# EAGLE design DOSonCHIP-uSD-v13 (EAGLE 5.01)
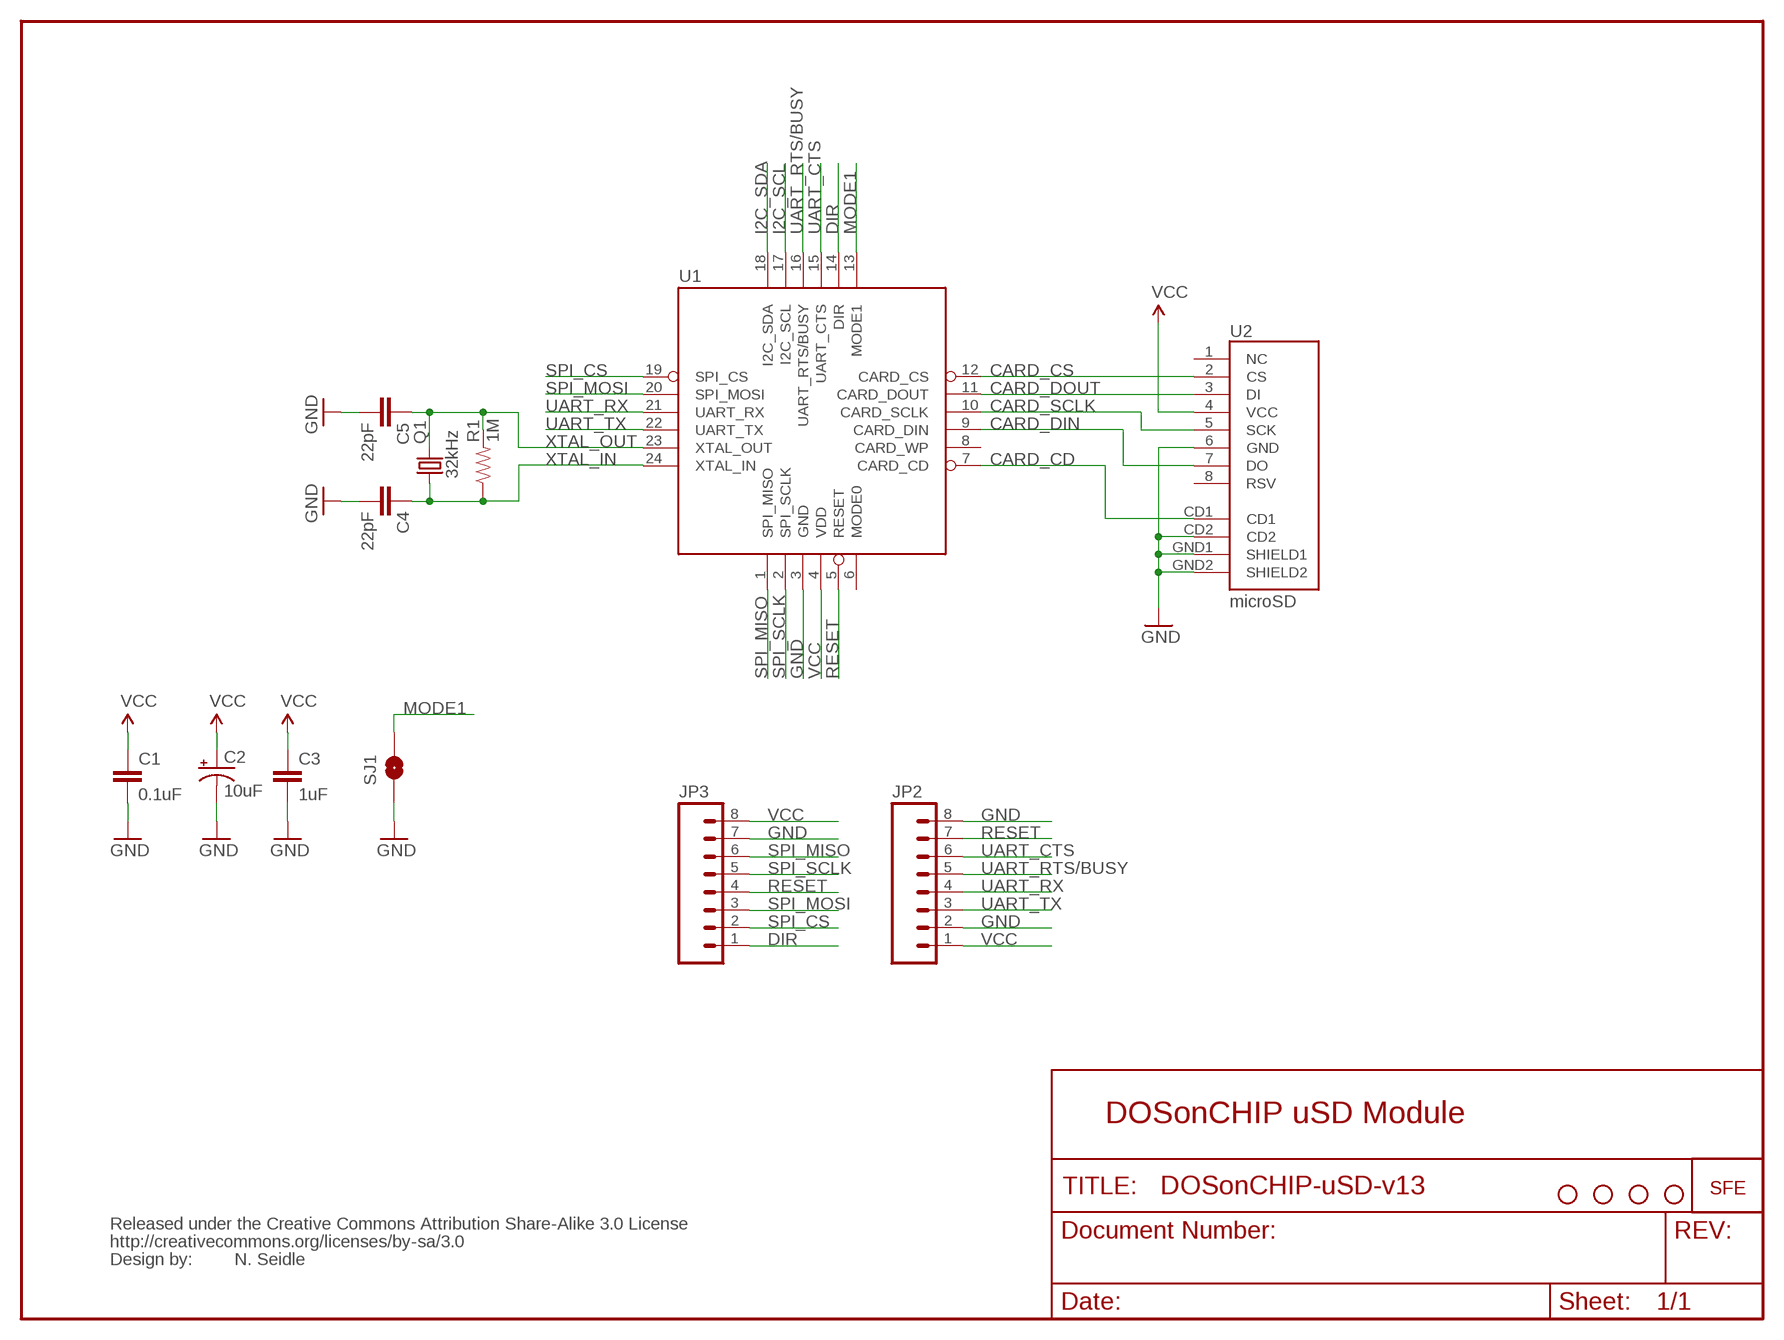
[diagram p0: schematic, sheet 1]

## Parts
C1  0.1uF  CAP0402  [C0402]
C2  10uF  CAP_POL1206  [EIA3216]
C3  1uF  CAP0402  [C0402]
C4  22pF  CAP0402  [C0402]
C5  22pF  CAP0402  [C0402]
JP2  M08  [1X08]
JP3  M08  [1X08]
Q1  32kHz  CRYSTAL32-SMD  [CRYSTAL-32KHZ-SMD]
R1  1M  RESISTOR0402  [C0402]
SJ1  SOLDERJUMPERNO2  [SJ_2S-NO]
U1  DOSONCHIP  DOSONCHIP-ICQFN  [QFN-24]
U2  microSD  USD-SOCKETUSD  [USD-SOCKET-PP]
U$1  LOGO-SFENEW  [SFE-NEW-WEBLOGO]
U$2  STAND-OFF  [STAND-OFF]
U$3  STAND-OFF  [STAND-OFF]
U$4  STAND-OFF  [STAND-OFF]
U$5  STAND-OFF  [STAND-OFF]
U$6  CREATIVE_COMMONS  [CREATIVE_COMMONS]

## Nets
CARD_CD: U1.7(CARD_CD) U2.CD1
CARD_CS: U1.12(CARD_CS) U2.2(CS)
CARD_DIN: U1.9(CARD_DIN) U2.7(DO)
CARD_DOUT: U1.11(CARD_DOUT) U2.3(DI)
CARD_SCLK: U1.10(CARD_SCLK) U2.5(SCK)
DIR: JP3.1 U1.14(DIR)
GND [power]: C1.2 C2.C(-) C3.2 C4.2 C5.2 JP2.2 JP2.8 JP3.7 SJ1.1 U1.3(GND) U2.6(GND) U2.CD2 U2.GND1(SHIELD1) U2.GND2(SHIELD2)
I2C_SCL: U1.17(I2C_SCL)
I2C_SDA: U1.18(I2C_SDA)
MODE1: SJ1.2 U1.13(MODE1)
RESET: JP2.7 JP3.4 U1.5(RESET)
SPI_CS: JP3.2 U1.19(SPI_CS)
SPI_MISO: JP3.6 U1.1(SPI_MISO)
SPI_MOSI: JP3.3 U1.20(SPI_MOSI)
SPI_SCLK: JP3.5 U1.2(SPI_SCLK)
UART_CTS: JP2.6 U1.15(UART_CTS)
UART_RTS/BUSY: JP2.5 U1.16(UART_RTS/BUSY)
UART_RX: JP2.4 U1.21(UART_RX)
UART_TX: JP2.3 U1.22(UART_TX)
VCC [power]: C1.1 C2.A(+) C3.1 JP2.1 JP3.8 U1.4(VDD) U2.4(VCC)
XTAL_IN: C4.1 Q1.X1 R1.1 U1.24(XTAL_IN)
XTAL_OUT: C5.1 Q1.X2 R1.2 U1.23(XTAL_OUT)
Unconnected: U1.6(MODE0) U1.8(CARD_WP) U2.1(NC) U2.8(RSV)

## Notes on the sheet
- DOSonCHIP uSD Module
- N. Seidle

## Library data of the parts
C1 C3-C5 = SparkFun:CAP: Capacitor
C2 = SparkFun:CAP_POL: Capacitor Polarized
JP2 JP3 = SparkFun:M08: Header 8 Standard 8-pin 0.1" header. Use with straight break away headers (SKU : PRT-00116), right angle break away headers (PRT-00553), swiss pins (PRT-00743), machine pins (PRT-00117), and female headers (PRT-00115).
Q1 = SparkFun:CRYSTAL: Crystals
R1 = SparkFun:RESISTOR: Resistor
SJ1 = SparkFun:SOLDERJUMPER: Solder Jumper
U1 = SparkFun:DOSONCHIP-IC: DOSonCHIP IC This is the tested schematic and footprint for the DOSonCHIP FAT16 FAT32 IC. Spark Fun Electronics SKU : COM-07956. QFN package also tested/proven.
U2 = SparkFun:USD-SOCKET: microSD Socket Push-push type uSD socket. Schematic element and footprint production proven. Spark Fun Electronics SKU : PRT-00127. tDoc lines correctly indicate media card edge positions when inserting (unlocked, locked, depressed).
U$1 = SparkFun:LOGO-SFE: Spark Fun Electronics PCB Logo
U$2-U$5 = SparkFun:STAND-OFF: Stand Off
U$6 = SparkFun:CREATIVE_COMMONS

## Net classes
0 default: width 0.203 mm
1 power: width 0.203 mm

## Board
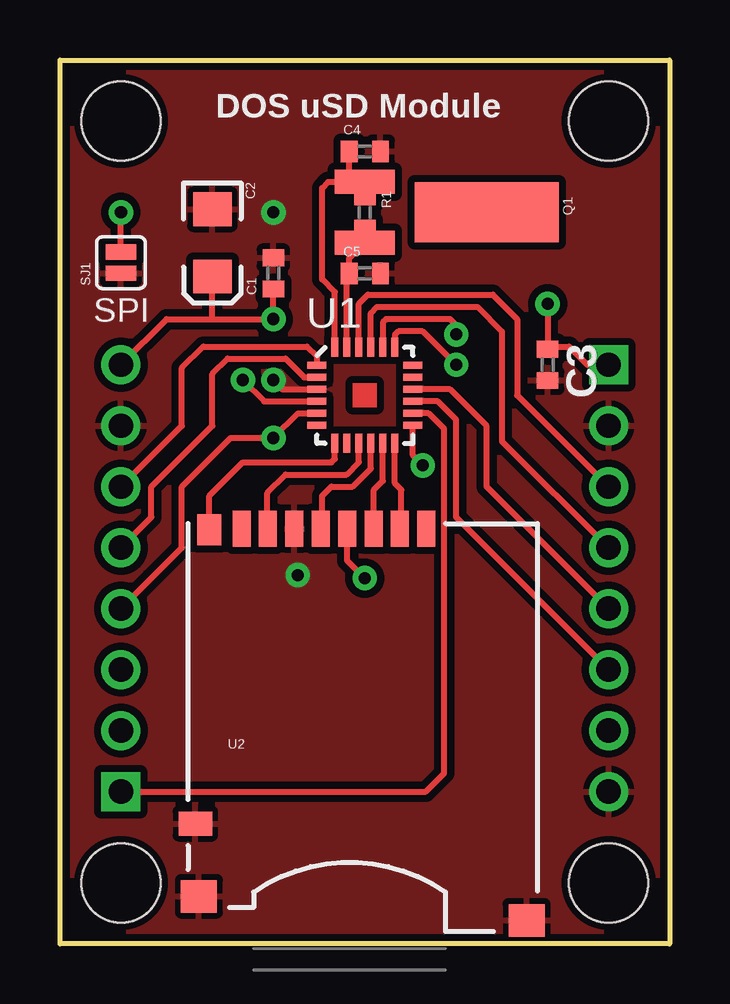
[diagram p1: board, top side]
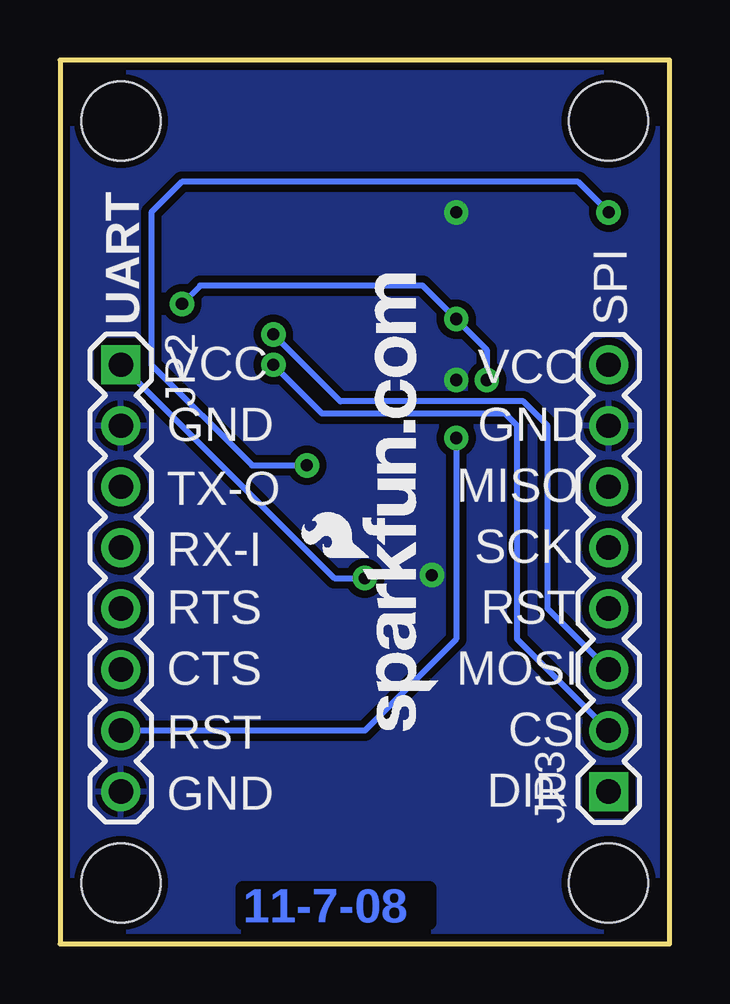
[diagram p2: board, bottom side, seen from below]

Size 25.4 x 36.83 mm. Coordinates in mm from the lower left corner, seen from the top.
Outline: 0,36.83 25.4,36.83 25.4,0 0,0 0,36.83
Copper layers (1*16): Top 0.035mm / dielectric 1.5mm / Bottom 0.035mm
Design rules "SparkFun": minimum track width 8mil, minimum drill 20mil, track to track 8mil, track to pad 8mil, pad to pad 7mil, via to via 8mil, smd to smd 8mil, copper to edge 10mil, drill to drill 8mil, minimum pad ring 12mil, minimum via ring 10mil, stop-mask expansion 4mil, vias tented up to drill 20mil, thermal gap 10mil

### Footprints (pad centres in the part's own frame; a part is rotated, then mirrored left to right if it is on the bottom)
C0402 = smd 0.7 x 0.9: 1 -0.65,0; 2 0.65,0
EIA3216 = smd 1.4 x 1.6: A 1.4,0; C -1.4,0
1X08 = drill 1.016 square: 1 0,0 | drill 1.016 round: 2 2.54,0; 3 5.08,0; 4 7.62,0; 5 10.16,0; 6 12.7,0; 7 15.24,0; 8 17.78,0
CRYSTAL-32KHZ-SMD = smd 2.5 x 6: SHEILD 0,5.08 | smd 1 x 2.5: X1 -1.27,0; X2 1.27,0
SJ_2S-NO = smd 0.635 x 1.27: 1 0,0; 2 0.889,0
QFN-24 = smd 0.8 x 0.3: 1 -2,1.25; 2 -2,0.75; 3 -2,0.25; 4 -2,-0.25; 5 -2,-0.75; 6 -2,-1.25; 13 2,-1.25; 14 2,-0.75; 15 2,-0.25; 16 2,0.25; 17 2,0.75; 18 2,1.25 | smd 0.3 x 0.8: 7 -1.25,-2; 8 -0.75,-2; 9 -0.25,-2; 10 0.25,-2; 11 0.75,-2; 12 1.25,-2; 19 1.25,2; 20 0.75,2; 21 0.25,2; 22 -0.25,2; 23 -0.75,2; 24 -1.25,2
USD-SOCKET-PP = smd 0.75 x 1.5: 1 3.2,16.8; 2 2.1,16.8; 3 1,16.8; 4 -0.1,16.8; 5 -1.2,16.8; 6 -2.3,16.8; 7 -3.4,16.8; 8 -4.5,16.8 | smd 1 x 1.3: CD1 -5.85,16.75 | smd 1.4 x 1: CD2 -6.425,4.5 | smd 1.5 x 1.35: GND1 -6.275,1.475; GND2 7.375,0.475
STAND-OFF = hole 3.302: 0,0

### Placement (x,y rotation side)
C1  8.89,27.94 90 top
C2  6.35,29.21 270 top
C3  20.32,24.13 270 top
C4  12.7,33.02 0 top
C5  12.7,27.94 0 top
JP2  22.86,24.13 270 bottom
JP3  2.54,6.35 90 bottom
Q1  12.7,30.48 270 top
R1  12.7,30.48 270 top
SJ1  2.54,27.94 90 top
U1  12.7,22.86 0 top
U2  12.06,0.51 0 top
U$1  9.65,8.89 90 bottom
U$2  2.54,2.54 0 top
U$3  22.86,2.54 0 top
U$4  22.86,34.29 0 top
U$5  2.54,34.29 0 top
U$6  not placed on the board

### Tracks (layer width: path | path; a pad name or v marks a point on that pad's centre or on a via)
CARD_CD
  Top 0.254: U1.7 11.45,20.21 11.3,20.07 7.62,20.07 6.22,18.67 6.22,17.27 U2.CD1
CARD_CS
  Top 0.254: U1.12 13.95,19.2 14.22,18.92 14.22,17.27 14.19,17.31 U2.2
CARD_DIN
  Top 0.254: U1.9 12.45,20.07 11.94,19.56 9.4,19.56 8.64,18.8 8.64,17.4 8.66,17.37 U2.7
CARD_DOUT
  Top 0.254: U1.11 13.45,19.29 13.08,18.92 13.08,17.4 13.06,17.38 U2.3
CARD_SCLK
  Top 0.254: U1.10 12.95,19.81 12.19,19.05 11.3,19.05 10.92,18.67 10.92,17.4 10.87,17.34 U2.5
DIR
  Top 0.254: U1.14 15.36,22.11 16,21.46 16,7.11 15.24,6.35 JP3.1
GND  (via drill 0.51)
  Top 0.254: U1.3 9.28,23.11 v8.89,23.5
  other vias: 8.89,30.48 9.91,15.37
  pour Top (isolate 0.305): 0,36.83 25.4,36.83 25.4,0 0,0
  pour Bottom (isolate 0.305): 0,36.83 25.4,36.83 25.4,0 0,0
MODE1  (via drill 0.51)
  Top 0.254: U1.13 14.7,20.35 v15.11,19.94 | SJ1.2 v2.54,30.48
  Bottom 0.254: v2.54,30.48 3.81,31.75 20.32,31.75 21.59,30.48 21.59,24.13 17.4,19.94 v15.11,19.94
RESET  (via drill 0.51)
  Top 0.254: U1.5 9.92,22.11 v8.89,21.08 7.11,21.08 5.08,19.05 5.08,16.51 JP3.4
  Bottom 0.254: v8.89,21.08 8.89,12.7 12.7,8.89 JP2.7
SPI_CS  (via drill 0.51)
  Top 0.254: U1.19 13.95,25.38 14.1,25.53 15.11,25.53 v16.51,24.13
  Bottom 0.254: JP3.2 6.35,12.7 6.35,21.59 6.86,22.1 14.48,22.1 v16.51,24.13
SPI_MISO
  Top 0.254: U1.1 10.7,24.48 10.29,24.89 5.97,24.89 5.08,24 5.08,21.59 JP3.6
SPI_MOSI  (via drill 0.51)
  Top 0.254: U1.20 13.45,25.9 13.59,26.04 16.26,26.04 16.51,25.78 v16.51,25.4
  Bottom 0.254: JP3.3 5.08,13.97 5.08,21.59 6.1,22.61 13.72,22.61 v16.51,25.4
SPI_SCLK
  Top 0.254: U1.2 10.17,23.61 9.4,24.38 6.99,24.38 6.35,23.75 6.35,21.59 3.81,19.05 3.81,17.78 JP3.5
UART_CTS
  Top 0.254: U1.15 15.74,22.61 16.51,21.84 16.51,17.78 JP2.6
UART_RTS/BUSY
  Top 0.254: U1.16 16.26,23.11 17.78,21.59 17.78,19.05 JP2.5
UART_RX
  Top 0.254: JP2.4 18.41,20.95 18.41,25.53 17.4,26.54 13.21,26.54 12.95,26.29 U1.21
UART_TX
  Top 0.254: JP2.3 19.05,22.86 19.05,26.04 18.03,27.05 12.83,27.05 12.45,26.67 U1.22
VCC  (via drill 0.51)
  Top 0.254: 20.32,24.89 21.21,24.89 21.97,24.13 JP2.1 | 20.05,24.78 C3.1 20.32,24.89 | U2.4 11.96,15.97 v12.7,15.24 | U1.4 8.51,22.61 v7.62,23.5 | C1.1 v8.89,26.04 6.35,26.04 | 6.35,26.04 4.45,26.04 JP3.8 | 6.35,26.04 C2.A | v20.32,26.67 20.32,24.89
  Bottom 0.254: v12.7,15.24 13.97,15.24 JP2.1 | v7.62,23.5 7.62,24.77 v8.89,26.04 10.29,27.43 19.56,27.43 v20.32,26.67
XTAL_IN
  Top 0.254: 12.06,31.75 11.18,31.75 10.92,31.5 10.92,27.69 11.45,27.16 U1.24 | 12.06,31.75 Q1.X1 R1.1 | C4.1 12.05,31.77 12.06,31.75
XTAL_OUT
  Top 0.254: U1.23 11.95,27.82 12.06,27.94 C5.1 12.05,28.56 Q1.X2 R1.2

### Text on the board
Bottom: 11-7-08
tPlace: DOS uSD Module | SPI | N. Seidle
bPlace: SPI | UART | VCC | VCC | GND | GND | MISO | TX-O | SCK | RX-I | RST | RTS | MOSI | CTS | CS | RST | DIR | GND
